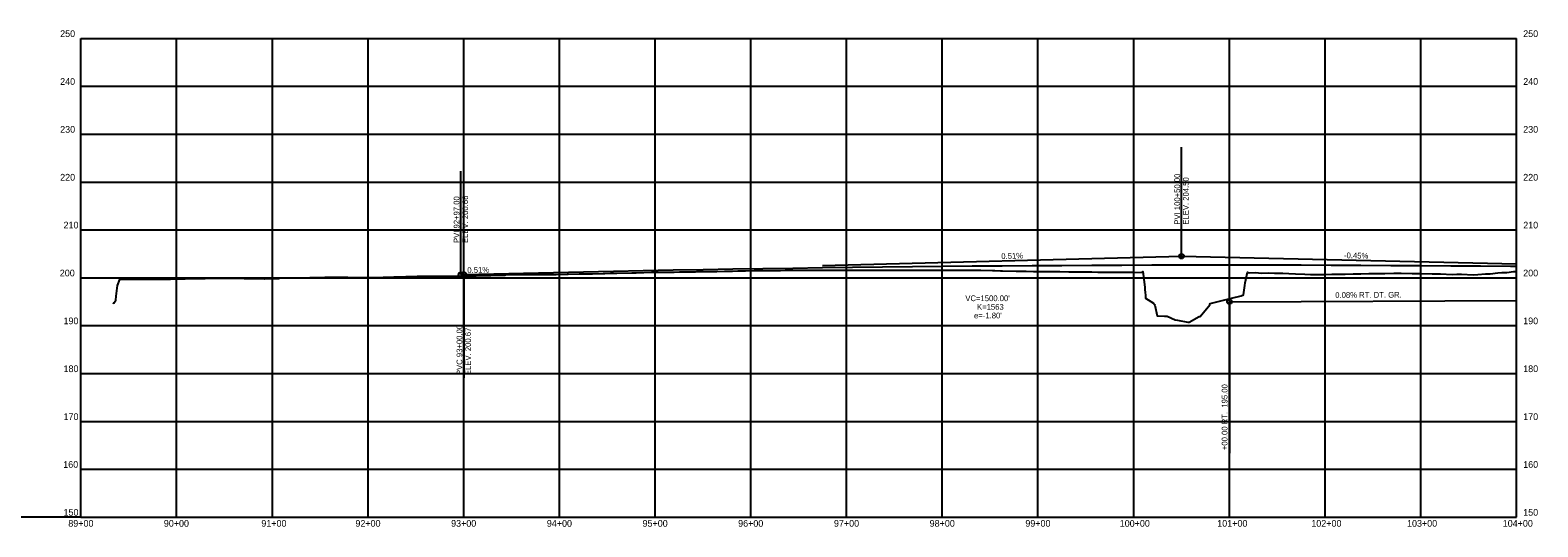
# Model space of a CAD drawing. Extents: x 1138442 to 1165793, y 1654070 to 1657687.
# Drawn here: x 1139958 to 1141533, y 1655756 to 1656275 of the extents above; entities that cross this region are included whole.
import ezdxf

# ---------------------------------------------------------------- set-up
doc = ezdxf.new("R2010")
doc.units = 0
for name, color, linetype in [('B_Dimensions', 7, 'Continuous'), ('R_Axis', 7, 'Continuous'), ('R_Axis Annot', 7, 'Continuous'), ('R_Grid', 7, 'Continuous'), ('R_Horz Alg Annot', 7, 'Continuous'), ('R_No Plot', 7, 'Continuous'), ('R_Proposed Const Limits_Hand', 7, 'Continuous'), ('R_Vert Alg Annot', 7, 'Continuous')]:
    doc.layers.add(name, color=color, linetype=linetype)

msp = doc.modelspace()

# ---------------------------------------------------------------- linework, layer by layer
at = {"layer": 'B_Dimensions'}
for p, q in [((1140785.9, 1656029.3), (1141160.9, 1656038.9)), ((1141160.9, 1656038.9), (1141510.9, 1656031)), ((1140407.9, 1656019.7), (1140410.9, 1656019.8)), ((1141210.9, 1655991.4), (1141510.9, 1655992.6))]:
    msp.add_line(p, q, dxfattribs=at)
msp.add_lwpolyline([(1140410.9, 1656019.8), (1140442.2, 1656020.5), (1140473.4, 1656021.3), (1140504.7, 1656022), (1140535.9, 1656022.7), (1140567.2, 1656023.3), (1140598.4, 1656024), (1140629.7, 1656024.6), (1140660.9, 1656025.1), (1140692.2, 1656025.7), (1140723.4, 1656026.2), (1140754.7, 1656026.6), (1140785.9, 1656027.1), (1140817.2, 1656027.5), (1140848.4, 1656027.8), (1140879.7, 1656028.2), (1140910.9, 1656028.5), (1140942.2, 1656028.8), (1140973.4, 1656029), (1141004.7, 1656029.3), (1141035.9, 1656029.4), (1141067.2, 1656029.6), (1141098.4, 1656029.7), (1141129.7, 1656029.8), (1141192.2, 1656029.9), (1141223.4, 1656029.9), (1141254.7, 1656029.9), (1141285.9, 1656029.8), (1141317.2, 1656029.7), (1141348.4, 1656029.6), (1141379.7, 1656029.4), (1141410.9, 1656029.3), (1141442.2, 1656029), (1141473.4, 1656028.8), (1141504.7, 1656028.5), (1141510.9, 1656028.4)], dxfattribs=at)
msp.add_circle((1141210.9, 1655991.4), 2.5, dxfattribs=at)
at = {"layer": 'R_Axis'}
for p, q in [((1140010.9, 1655766.4), (1140010.9, 1656266.4)), ((1141510.9, 1655766.4), (1141510.9, 1656266.4)), ((1140010.9, 1655766.4), (1141510.9, 1655766.4))]:
    msp.add_line(p, q, dxfattribs=at)
at = {"layer": 'R_Grid'}
for p, q in [((1140010.9, 1656266.4), (1141510.9, 1656266.4)), ((1140010.9, 1656266.4), (1141510.9, 1656266.4)), ((1140110.9, 1655766.4), (1140110.9, 1656266.4)), ((1140210.9, 1655766.4), (1140210.9, 1656266.4)), ((1140310.9, 1655766.4), (1140310.9, 1656266.4)), ((1140410.9, 1655766.4), (1140410.9, 1656266.4)), ((1140510.9, 1655766.4), (1140510.9, 1656266.4)), ((1140610.9, 1655766.4), (1140610.9, 1656266.4)), ((1140710.9, 1655766.4), (1140710.9, 1656266.4)), ((1140810.9, 1655766.4), (1140810.9, 1656266.4)), ((1140910.9, 1655766.4), (1140910.9, 1656266.4)), ((1141010.9, 1655766.4), (1141010.9, 1656266.4)), ((1141110.9, 1655766.4), (1141110.9, 1656266.4)), ((1141210.9, 1655766.4), (1141210.9, 1656266.4)), ((1141310.9, 1655766.4), (1141310.9, 1656266.4)), ((1141410.9, 1655766.4), (1141410.9, 1656266.4)), ((1140010.9, 1656216.4), (1141510.9, 1656216.4)), ((1140010.9, 1656166.4), (1141510.9, 1656166.4)), ((1140010.9, 1656116.4), (1141510.9, 1656116.4)), ((1140010.9, 1656066.4), (1141510.9, 1656066.4)), ((1140010.9, 1656016.4), (1141510.9, 1656016.4)), ((1140010.9, 1655966.4), (1141510.9, 1655966.4)), ((1140010.9, 1655916.4), (1141510.9, 1655916.4)), ((1140010.9, 1655866.4), (1141510.9, 1655866.4)), ((1140010.9, 1655816.4), (1141510.9, 1655816.4))]:
    msp.add_line(p, q, dxfattribs=at)
at = {"layer": 'R_No Plot'}
msp.add_line((1140010.9, 1655766.4), (1138441.8, 1655766.4), dxfattribs=at)
at = {"layer": 'R_Proposed Const Limits_Hand'}
msp.add_lwpolyline([(1140044.4, 1655990.3), (1140045.2, 1655989.9), (1140047.3, 1655993), (1140047.8, 1655997.1), (1140049.2, 1656008.5), (1140051.4, 1656014.7), (1140070.3, 1656014.9), (1140071.2, 1656014.9), (1140089, 1656015.1), (1140090.6, 1656015.1), (1140104.4, 1656015.1), (1140119, 1656015.2), (1140119.7, 1656015.2), (1140139.9, 1656015.6), (1140140.3, 1656015.6), (1140140.7, 1656015.6), (1140159.3, 1656016), (1140160.9, 1656016.1), (1140160.9, 1656016.1), (1140163.1, 1656016), (1140181.6, 1656015.7), (1140181.9, 1656015.7), (1140202.3, 1656015.4), (1140202.7, 1656015.4), (1140218.1, 1656015.8), (1140218.5, 1656015.9), (1140234, 1656016.3), (1140234.3, 1656016.3), (1140249.9, 1656016.7), (1140265.6, 1656017.2), (1140265.7, 1656017.2), (1140283.2, 1656017.1), (1140289.6, 1656017), (1140289.7, 1656017), (1140313.3, 1656016.8), (1140313.6, 1656016.8), (1140326.6, 1656017.2), (1140337.7, 1656017.5), (1140338, 1656017.5), (1140338.2, 1656017.5), (1140362.3, 1656018.2), (1140363.2, 1656018.2), (1140385.5, 1656018.2), (1140397.3, 1656018.2), (1140408.7, 1656018.1), (1140408.7, 1656018.1), (1140423.6, 1656018.5), (1140424, 1656018.5), (1140430.9, 1656018.7), (1140438.7, 1656018.9), (1140439.2, 1656018.9), (1140453.1, 1656019.3), (1140453.7, 1656019.3), (1140454.5, 1656019.4), (1140468.7, 1656019.7), (1140469.7, 1656019.8), (1140475.3, 1656019.8), (1140481.4, 1656019.8), (1140482.3, 1656019.9), (1140493.9, 1656019.9), (1140494.9, 1656019.9), (1140497.6, 1656020), (1140506.4, 1656020), (1140507.5, 1656020), (1140518.8, 1656020.1), (1140519.8, 1656020.1), (1140520.1, 1656020.1), (1140531.4, 1656020.4), (1140532.8, 1656020.4), (1140542, 1656020.6), (1140544, 1656020.7), (1140545.5, 1656020.7), (1140556.6, 1656020.9), (1140558.2, 1656021), (1140564.2, 1656021.1), (1140569.2, 1656021.2), (1140571, 1656021.2), (1140586.4, 1656021.6), (1140587.9, 1656021.6), (1140591.2, 1656021.7), (1140607.2, 1656022.1), (1140608.6, 1656022.1), (1140611.3, 1656022.2), (1140622.2, 1656022.3), (1140625.7, 1656022.4), (1140630.8, 1656022.4), (1140636.2, 1656022.5), (1140640.1, 1656022.6), (1140650.1, 1656022.7), (1140653, 1656022.7), (1140654.6, 1656022.8), (1140664.1, 1656022.9), (1140669, 1656023), (1140675.2, 1656023.1), (1140683.4, 1656023.4), (1140691.7, 1656023.4), (1140697.4, 1656023.6), (1140705.2, 1656023.8), (1140714.3, 1656023.9), (1140719.6, 1656023.9), (1140724, 1656024), (1140735.9, 1656024), (1140741.8, 1656024.1), (1140746.9, 1656024.2), (1140757.5, 1656024.2), (1140764, 1656024.2), (1140764.7, 1656024.2), (1140775, 1656024.3), (1140782.6, 1656024.3), (1140786.2, 1656024.3), (1140790.8, 1656024.3), (1140799.2, 1656024.3), (1140807.8, 1656024.3), (1140808.4, 1656024.3), (1140813.6, 1656024.3), (1140829.4, 1656024.2), (1140830.9, 1656024.3), (1140834.1, 1656024.3), (1140851.1, 1656024.2), (1140853.4, 1656024.2), (1140855.3, 1656024.2), (1140875.6, 1656024.3), (1140875.9, 1656024.3), (1140898.3, 1656024.4), (1140899.1, 1656024.4), (1140900, 1656024.4), (1140912, 1656024.4), (1140919, 1656024.5), (1140920.8, 1656024.4), (1140923.7, 1656024.4), (1140932.7, 1656024.3), (1140943.3, 1656024.3), (1140947.4, 1656024.3), (1140951.3, 1656024.2), (1140963.3, 1656024), (1140965.7, 1656024), (1140971.6, 1656023.8), (1140973.7, 1656023.8), (1140988.2, 1656023.4), (1140993.2, 1656023.3), (1140998.5, 1656023.2), (1141006.3, 1656023.1), (1141010.7, 1656023.1), (1141012.8, 1656023), (1141019.8, 1656023), (1141027.7, 1656022.9), (1141033.2, 1656022.8), (1141033.6, 1656022.8), (1141043.1, 1656022.7), (1141048, 1656022.6), (1141053.6, 1656022.5), (1141055.6, 1656022.5), (1141067.3, 1656022.5), (1141073.6, 1656022.4), (1141078.1, 1656022.4), (1141086.4, 1656022.4), (1141091.9, 1656022.3), (1141099.2, 1656022.4), (1141100.6, 1656022.3), (1141106, 1656022.2), (1141111.7, 1656022.3), (1141120.2, 1656021.9), (1141120.6, 1656022.9), (1141122.5, 1656006.5), (1141122.6, 1656003.8), (1141122.8, 1656001.5), (1141123.1, 1655997.9), (1141123.3, 1655995), (1141131.6, 1655989.9), (1141132.7, 1655988.5), (1141132.9, 1655987.7), (1141135.4, 1655976.7), (1141143.1, 1655976.4), (1141145.5, 1655976.2), (1141145.8, 1655976.2), (1141154.1, 1655972.6), (1141156.7, 1655972.2), (1141167.4, 1655970), (1141168, 1655969.9), (1141168.8, 1655969.9), (1141179.2, 1655975.8), (1141180.4, 1655975.9), (1141190.3, 1655988.3), (1141190.5, 1655988.7), (1141190.9, 1655989.5), (1141213, 1655995), (1141223.2, 1655997.5), (1141225.8, 1655998.7), (1141227.1, 1656008.5), (1141227.5, 1656011.2), (1141229.8, 1656022.4), (1141231.4, 1656021.5), (1141238.5, 1656021.8), (1141244, 1656021.3), (1141251.5, 1656021.5), (1141257.9, 1656021.4), (1141266.8, 1656021.1), (1141273, 1656021), (1141280.1, 1656020.6), (1141289.6, 1656020.3), (1141295.8, 1656020), (1141310.1, 1656020), (1141318, 1656020.3), (1141332, 1656020.3), (1141340.2, 1656020.6), (1141348.3, 1656020.7), (1141356.7, 1656020.8), (1141365.3, 1656021), (1141373.4, 1656021), (1141382.8, 1656021.2), (1141390.4, 1656021.3), (1141401.8, 1656020.9), (1141411.1, 1656020.9), (1141422.8, 1656020.4), (1141431.6, 1656020.5), (1141443.7, 1656020), (1141448.6, 1656020.1), (1141453.5, 1656020.1), (1141465.6, 1656019.6), (1141470.5, 1656019.7), (1141478.4, 1656020.6), (1141480.3, 1656020.7), (1141483.5, 1656020.7), (1141491.3, 1656021.6), (1141495.4, 1656021.8), (1141500.7, 1656022), (1141507.9, 1656022.8), (1141510.6, 1656023.1), (1141510.9, 1656023.1)], dxfattribs=at)
at = {"layer": 'R_Vert Alg Annot'}
for p, q in [((1141160.9, 1656068.9), (1141160.9, 1656152.9)), ((1140407.9, 1656049.7), (1140407.9, 1656127.7)), ((1141160.9, 1656038.9), (1141160.9, 1656068.9)), ((1140407.9, 1656019.7), (1140407.9, 1656049.7)), ((1140410.9, 1656019.8), (1140410.9, 1655989.8)), ((1140410.9, 1655989.8), (1140410.9, 1655911.8)), ((1141210.9, 1655991.4), (1141210.9, 1655966.4)), ((1141210.9, 1655966.4), (1141210.9, 1655833.4))]:
    msp.add_line(p, q, dxfattribs=at)
for centre in [(1141160.9, 1656038.9), (1140407.9, 1656019.7), (1140410.9, 1656019.8)]:
    msp.add_circle(centre, 2.5, dxfattribs=at)

# ---------------------------------------------------------------- texts
at = {"layer": 'R_Axis Annot'}
for s, height, p in [('250', 7, (1139989.2, 1656267.9)), ('250', 7, (1139989.2, 1656267.9)), ('250', 7, (1141517.9, 1656267.9)), ('250', 7, (1141517.9, 1656267.9)), ('240', 7, (1139989.2, 1656217.9)), ('240', 7, (1141517.9, 1656217.9)), ('230', 7, (1139989.2, 1656167.9)), ('230', 7, (1141517.9, 1656167.9)), ('220', 7, (1139989.2, 1656117.9)), ('220', 7, (1141517.9, 1656117.9)), ('210', 7, (1139992.7, 1656067.9)), ('210', 7, (1141517.9, 1656067.9)), ('200', 7, (1139988.8, 1656017.9)), ('200', 7, (1141517.9, 1656017.9)), ('190', 7, (1139992.7, 1655967.9)), ('190', 7, (1141517.9, 1655967.9)), ('180', 7, (1139992.7, 1655917.9)), ('180', 7, (1141517.9, 1655917.9)), ('170', 7, (1139992.7, 1655867.9)), ('170', 7, (1141517.9, 1655867.9)), ('160', 7, (1139992.4, 1655817.9)), ('160', 7, (1141517.9, 1655817.9)), ('150', 7, (1139992.7, 1655767.9)), ('150', 7, (1141517.9, 1655767.9)), ('89+00', 7, (1139997.7, 1655756.4)), ('-', 0.0001, (1140010.9, 1655766.4)), ('90+00', 7, (1140097.5, 1655756.4)), ('91+00', 7, (1140199.4, 1655756.4)), ('92+00', 7, (1140297.7, 1655756.4)), ('93+00', 7, (1140397.7, 1655756.4)), ('94+00', 7, (1140497.7, 1655756.4)), ('95+00', 7, (1140597.7, 1655756.4)), ('96+00', 7, (1140697.6, 1655756.4)), ('97+00', 7, (1140797.7, 1655756.4)), ('98+00', 7, (1140897.7, 1655756.4)), ('99+00', 7, (1140997.7, 1655756.4)), ('100+00', 7, (1141096.3, 1655756.4)), ('101+00', 7, (1141198.2, 1655756.4)), ('102+00', 7, (1141296.5, 1655756.4)), ('103+00', 7, (1141396.5, 1655756.4)), ('104+00', 7, (1141496.5, 1655756.4))]:
    msp.add_text(s, height=height, dxfattribs=at).set_placement(p)
at = {"layer": 'R_Horz Alg Annot'}
for s, rotation, p in [('0.51%', 1.5104, (1140972.6, 1656036)), ('-0.45%', 358.698, (1141330.6, 1656036.9))]:
    msp.add_text(s, height=6, rotation=rotation, dxfattribs=at).set_placement(p)
at = {"layer": 'R_Vert Alg Annot'}
for s, rotation, p in [('PVI 100+50.00', 90, (1141159.4, 1656071.9)), ('ELEV. 204.50', 90, (1141168.4, 1656071.9)), ('PVI 92+97.00', 90, (1140406.4, 1656052.7)), ('ELEV. 200.66', 90, (1140415.4, 1656052.7)), ('0.51%', 1.4607, (1140414.7, 1656021.3)), ('0.08% RT. DT. GR.', 0.2349, (1141321.5, 1655995.4)), ('PVC 93+00.00', 90, (1140409.4, 1655914.8)), ('ELEV. 200.67', 90, (1140418.4, 1655914.8)), ('+00.00 RT.  195.00', 90, (1141208.9, 1655836.4))]:
    msp.add_text(s, height=6, rotation=rotation, dxfattribs=at).set_placement(p)
for s, p in [("VC=1500.00'", (1140935, 1655992)), ("e=-1.80'", (1140944.1, 1655974)), ('K=1563', (1140947.2, 1655983))]:
    msp.add_text(s, height=6, dxfattribs=at).set_placement(p)

doc.saveas('drawing.dxf')
